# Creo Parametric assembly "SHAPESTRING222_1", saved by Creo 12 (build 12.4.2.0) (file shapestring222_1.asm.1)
Units: Custom; MM, KILOGRAM, SECS

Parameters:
  PTC_WM_ITERATION = "0"
  PTC_WM_VERSION = "-.0"
  PTC_WM_LIFECYCLE_STATE = "In Work"
  PTC_WM_LIFECYCLE = "MO_CADDocument"
  PTC_WM_CREATED_BY = "Maximilian Roepper (Z0017RMS: MO)"
  PTC_WM_CREATED_ON = "18-Sep-26 11:36:42 AM"
  PTC_WM_MODIFIED_BY = "Maximilian Roepper (Z0017RMS: MO)"
  PTC_WM_MODIFIED_ON = "18-Sep-26 11:36:46 AM"
  PDMLINKNUMBER = "PDM000071454916"
  PTC_WM_NUMBER = "PDM000071454916"

Other parameters: WEIGHT, WEIGHT_FACTOR, WEIGHT_ADD, MC_ERRORS, SUPPLIER

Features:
  1. coordinate system
  2. imported feature
  3. component "SHAPESTRING086_1"
  4. component "SHAPESTRING197_1"
  5. component "SHAPESTRING198_1"
  6. component "SHAPESTRING199_1"
  7. component "SHAPESTRING200_1"
  8. component "SHAPESTRING201_1"
  9. component "SHAPESTRING202_1"
  10. component "SHAPESTRING203_1"
  11. component "SHAPESTRING204_1"
  12. component "SHAPESTRING205_1"
  13. component "SHAPESTRING206_1"
  14. component "SHAPESTRING207_1"
  15. component "SHAPESTRING208_1"
  16. component "SHAPESTRING209_1"
  17. component "SHAPESTRING210_1"
  18. component "SHAPESTRING211_1"
  19. component "SHAPESTRING212_1"
  20. component "SHAPESTRING213_1"
  21. component "SHAPESTRING214_1"
  22. component "SHAPESTRING215_1"
  23. component "SHAPESTRING216_1"
  24. component "SHAPESTRING217_1"
  25. component "SHAPESTRING218_1"
  26. component "SHAPESTRING219_1"
  27. component "SHAPESTRING220_1"
  28. component "SHAPESTRING221_1"

Other named items: DRW_VIEW_ORG, ROUGH-GROB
